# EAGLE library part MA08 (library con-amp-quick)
AMP QUICK CONNECTOR
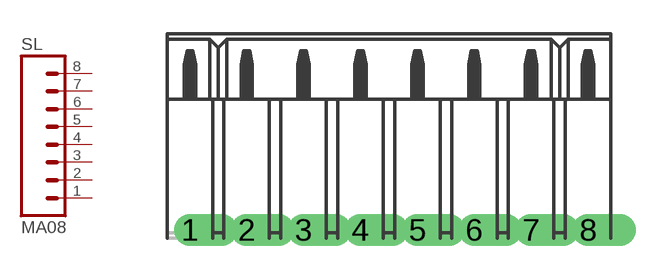
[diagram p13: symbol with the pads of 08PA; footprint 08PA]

Designator prefix SL

## MA08  [08PA]
1  1  pas
2  2  pas
3  3  pas
4  4  pas
5  5  pas
6  6  pas
7  7  pas
8  8  pas

## Footprint 08PA (pad centres in mm)
AMP QUICK CONNECTOR
drill 0.914 offset: 1 -8.89,0; 2 -6.35,0; 3 -3.81,0; 4 -1.27,0; 5 1.27,0; 6 3.81,0; 7 6.35,0; 8 8.89,0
